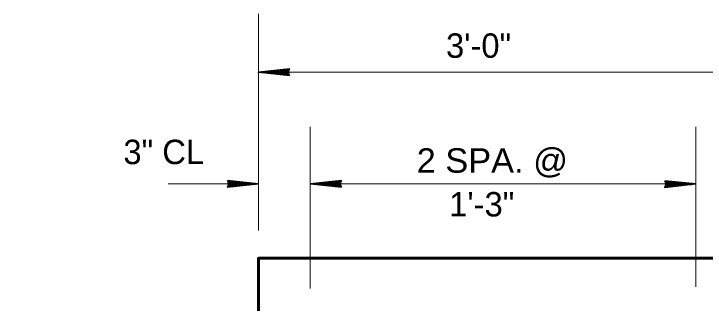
# Model space of a CAD drawing. Extents: x 6.34 to 9.53, y -1.46 to 0.53.
# Drawn here: x 7.7101 to 7.9456, y -0.4048 to -0.3062 of the extents above; entities that cross this region are included whole.
import ezdxf

# ---------------------------------------------------------------- set-up
doc = ezdxf.new("R2010")
doc.units = 0
doc.header["$LTSCALE"] = 0.0033
doc.layers.add('1', color=7, linetype='Continuous', lineweight=40)

msp = doc.modelspace()

# ---------------------------------------------------------------- linework, layer by layer
at = {"layer": '1', "lineweight": 13}
for p, q in [((7.793417, -0.38), (7.793417, -0.306167)), ((7.793667, -0.326083), (7.960083, -0.326083)), ((7.811083, -0.39975), (7.811083, -0.344667)), ((7.942417, -0.39925), (7.942417, -0.344667)), ((7.762667, -0.364083), (7.7835, -0.364083)), ((7.810917, -0.364167), (7.941833, -0.364167))]:
    msp.add_line(p, q, dxfattribs=at)
at = {"layer": '1', "lineweight": 35}
for p, q in [((7.80375, -0.325), (7.796417, -0.325833)), ((7.804, -0.326083), (7.793417, -0.326083)), ((7.80375, -0.326917), (7.795917, -0.325917)), ((7.80375, -0.326917), (7.795917, -0.326083)), ((7.80375, -0.327083), (7.795917, -0.326167)), ((7.80375, -0.327083), (7.795917, -0.326167)), ((7.80375, -0.327), (7.795917, -0.326167)), ((7.80375, -0.325167), (7.796417, -0.325917)), ((7.80375, -0.32525), (7.796417, -0.326083)), ((7.803833, -0.325417), (7.7965, -0.326167)), ((7.782833, -0.364083), (7.793417, -0.364083)), ((7.783, -0.36475), (7.790333, -0.364)), ((7.783083, -0.363083), (7.790917, -0.364)), ((7.783083, -0.363083), (7.790917, -0.364)), ((7.783083, -0.363167), (7.790917, -0.364)), ((7.783083, -0.36325), (7.790917, -0.364083)), ((7.783083, -0.36325), (7.790917, -0.36425)), ((7.783083, -0.364917), (7.790417, -0.364083)), ((7.783083, -0.365), (7.790417, -0.36425)), ((7.783083, -0.365167), (7.790417, -0.364333)), ((7.821667, -0.364167), (7.811083, -0.364167)), ((7.821417, -0.365), (7.813583, -0.364)), ((7.821417, -0.365), (7.813583, -0.364167)), ((7.821417, -0.365167), (7.813583, -0.36425)), ((7.821417, -0.365167), (7.813583, -0.36425)), ((7.821417, -0.365083), (7.813583, -0.36425)), ((7.821417, -0.363083), (7.814083, -0.363917)), ((7.821417, -0.36325), (7.814083, -0.364)), ((7.821417, -0.363333), (7.814083, -0.364167)), ((7.8215, -0.3635), (7.814167, -0.36425)), ((7.931833, -0.364167), (7.942417, -0.364167)), ((7.932, -0.364833), (7.939333, -0.364083)), ((7.932083, -0.363167), (7.939917, -0.364083)), ((7.932083, -0.363167), (7.939917, -0.364083)), ((7.932083, -0.36325), (7.939917, -0.364083)), ((7.932083, -0.363333), (7.939917, -0.364167)), ((7.932083, -0.363333), (7.939917, -0.364333)), ((7.932083, -0.365), (7.939417, -0.364167)), ((7.932083, -0.365083), (7.939417, -0.364333)), ((7.932083, -0.36525), (7.939417, -0.364417))]:
    msp.add_line(p, q, dxfattribs=at)
for points in [[(7.804, -0.327167), (7.793417, -0.326083), (7.804, -0.324917), (7.803417, -0.326083)], [(7.80325, -0.326167), (7.798583, -0.32625), (7.798583, -0.326167), (7.7995, -0.326167), (7.80325, -0.32625), (7.80025, -0.326333), (7.803417, -0.326417), (7.801167, -0.3265), (7.803417, -0.326583), (7.799917, -0.326333), (7.79525, -0.326167), (7.796167, -0.325917), (7.794917, -0.325917), (7.80325, -0.325917), (7.800833, -0.32575), (7.803417, -0.32575), (7.798083, -0.326167), (7.803417, -0.3255)], [(7.782833, -0.363), (7.793417, -0.364083), (7.782833, -0.36525), (7.783417, -0.364083)], [(7.783583, -0.364), (7.78825, -0.363917), (7.78825, -0.364), (7.787333, -0.364), (7.783583, -0.363917), (7.786583, -0.363833), (7.783417, -0.36375), (7.785667, -0.363667), (7.783417, -0.363583), (7.786917, -0.363833), (7.791583, -0.364), (7.790667, -0.36425), (7.791917, -0.36425), (7.783583, -0.36425), (7.786, -0.364417), (7.783417, -0.364417), (7.78875, -0.364), (7.783417, -0.364667)], [(7.821667, -0.36525), (7.811083, -0.364167), (7.821667, -0.363), (7.821083, -0.364167)], [(7.820917, -0.36425), (7.81625, -0.364333), (7.81625, -0.36425), (7.817167, -0.36425), (7.820917, -0.364333), (7.817917, -0.364417), (7.821083, -0.3645), (7.818833, -0.364583), (7.821083, -0.364667), (7.817583, -0.364417), (7.812917, -0.36425), (7.813833, -0.364), (7.812583, -0.364), (7.820917, -0.364), (7.8185, -0.363833), (7.821083, -0.363833), (7.81575, -0.36425), (7.821083, -0.363583)], [(7.931833, -0.363083), (7.942417, -0.364167), (7.931833, -0.365333), (7.932417, -0.364167)], [(7.932583, -0.364083), (7.93725, -0.364), (7.93725, -0.364083), (7.936333, -0.364083), (7.932583, -0.364), (7.935583, -0.363917), (7.932417, -0.363833), (7.934667, -0.36375), (7.932417, -0.363667), (7.935917, -0.363917), (7.940583, -0.364083), (7.939667, -0.364333), (7.940917, -0.364333), (7.932583, -0.364333), (7.935, -0.3645), (7.932417, -0.3645), (7.93775, -0.364083), (7.932417, -0.36475)]]:
    msp.add_lwpolyline(points, close=True, dxfattribs=at)
for points in [[(7.80325, -0.326167), (7.803667, -0.326917), (7.803417, -0.326667), (7.80325, -0.326333), (7.803, -0.326417), (7.803167, -0.32675), (7.803333, -0.326), (7.8035, -0.3255), (7.80375, -0.325083)], [(7.783583, -0.364), (7.783167, -0.36325), (7.783417, -0.3635), (7.783583, -0.363833), (7.783833, -0.36375), (7.783667, -0.363417), (7.7835, -0.364167), (7.783333, -0.364667), (7.783083, -0.365083)], [(7.820917, -0.36425), (7.821333, -0.365), (7.821083, -0.36475), (7.820917, -0.364417), (7.820667, -0.3645), (7.820833, -0.364833), (7.821, -0.364083), (7.821167, -0.363583), (7.821417, -0.363167)], [(7.932583, -0.364083), (7.932167, -0.363333), (7.932417, -0.363583), (7.932583, -0.363917), (7.932833, -0.363833), (7.932667, -0.3635), (7.9325, -0.36425), (7.932333, -0.36475), (7.932083, -0.365167)]]:
    msp.add_lwpolyline(points, dxfattribs=at)
at = {"layer": '1', "lineweight": 60}
msp.add_lwpolyline([(7.710083, -0.722833), (7.793417, -0.722833), (7.793417, -0.3895), (7.960083, -0.3895), (7.960083, -0.722833), (8.043417, -0.722833)], dxfattribs=at)

# ---------------------------------------------------------------- texts
at = {"layer": '1'}
for s, height, p in [('3\'-0"', 0.008333, (7.857333, -0.321167)), ('3" CL', 0.008334, (7.747417, -0.357417)), ('1\'-3"', 0.008334, (7.858417, -0.37525))]:
    msp.add_text(s, height=height, dxfattribs=at).set_placement(p)
at = {"layer": '1', "width": 1.05}
msp.add_text('2 SPA. @ ', height=0.008334, dxfattribs=at).set_placement((7.847333, -0.360333))

doc.saveas('drawing.dxf')
